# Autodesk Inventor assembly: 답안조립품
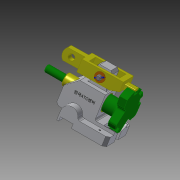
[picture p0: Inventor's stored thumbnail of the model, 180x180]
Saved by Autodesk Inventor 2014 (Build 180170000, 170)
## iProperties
Created: 2016-11
Part Number: 답안조립품
Document SubType Name: Assembly
Designer: USER
Author: USER
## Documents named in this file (8)
- C:\Users\USER\Desktop\461108V1032\답안조립품.iam
- C:\Users\USER\Desktop\461108V1032\본체.ipt
- C:\Users\USER\Desktop\461108V1032\부시.ipt
- C:\Users\USER\Desktop\461108V1032\분할대.ipt
- C:\Users\USER\Desktop\461108V1032\분할축.ipt
- C:\Users\USER\Desktop\461108V1032\와셔.ipt
- C:\Users\USER\Desktop\461108V1032\원통형핀.ipt
- C:\Users\USER\Desktop\461108V1032\클레비스핀.ipt
